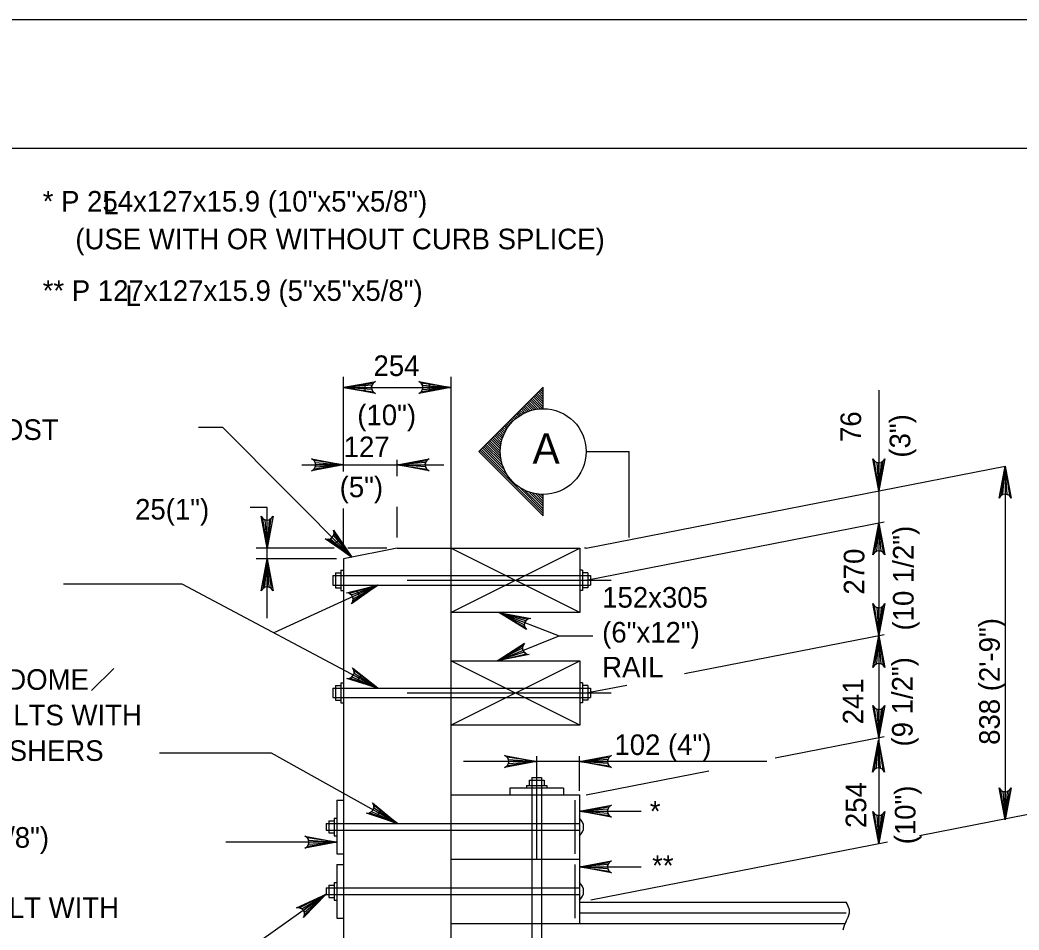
# Model space of a CAD drawing. Extents: x 0 to 36.3, y -66 to 0.
# Drawn here: x 5.26 to 11.08, y -5.3 to 0 of the extents above; entities that cross this region are included whole.
import ezdxf

# ---------------------------------------------------------------- set-up
doc = ezdxf.new("R2010")
doc.units = 0
for name, color, linetype in [('1', 7, 'Continuous'), ('2', 7, 'Continuous'), ('3', 7, 'Continuous'), ('63', 7, 'Continuous')]:
    doc.layers.add(name, color=color, linetype=linetype)

msp = doc.modelspace()

# ---------------------------------------------------------------- linework, layer by layer
at = {"layer": '1'}
msp.add_lwpolyline([(1.75, -21.25), (33.25, -21.25), (33.25, -0.75), (1.75, -0.75)], close=True, dxfattribs=at)
at = {"layer": '2'}
for p, q in [((7.4603, -3.0782), (7.1478, -3.1407)), ((7.4603, -3.0782), (7.7728, -3.0782)), ((8.5244, -3.4532), (7.7728, -3.0782)), ((7.7728, -3.4532), (8.5244, -3.0782)), ((7.7728, -3.0782), (7.7728, -6.0157)), ((7.7728, -3.0782), (8.5244, -3.0782)), ((8.5244, -3.0782), (8.5244, -3.4532)), ((7.1478, -3.1407), (7.1478, -6.0157)), ((7.0853, -3.2383), (7.0853, -3.293)), ((7.0853, -3.2383), (8.5866, -3.2383)), ((7.101, -3.2227), (7.101, -3.3087)), ((7.101, -3.2227), (7.1322, -3.2227)), ((7.1322, -3.2071), (7.1478, -3.2071)), ((7.1322, -3.2071), (7.1322, -3.3242)), ((8.5397, -3.2071), (8.5241, -3.2071)), ((8.5397, -3.2071), (8.5397, -3.3242)), ((8.571, -3.2227), (8.5397, -3.2227)), ((8.571, -3.2227), (8.571, -3.3087)), ((8.5866, -3.2383), (8.5866, -3.293)), ((7.0853, -3.293), (8.5866, -3.293)), ((7.101, -3.3087), (7.1322, -3.3087)), ((8.571, -3.3087), (8.5397, -3.3087)), ((7.1322, -3.3242), (7.1478, -3.3242)), ((8.5397, -3.3242), (8.5241, -3.3242)), ((8.5244, -3.4532), (7.7728, -3.4532)), ((7.7728, -4.1094), (8.5244, -3.7344)), ((8.5244, -4.1094), (7.7728, -3.7344)), ((7.7728, -3.7344), (8.5244, -3.7344)), ((8.5244, -3.7344), (8.5244, -4.1094)), ((7.0853, -3.8946), (7.0853, -3.9492)), ((7.0853, -3.8946), (8.5866, -3.8946)), ((7.101, -3.8789), (7.1322, -3.8789)), ((7.101, -3.8789), (7.101, -3.9649)), ((7.1322, -3.8633), (7.1322, -3.9805)), ((7.1322, -3.8633), (7.1478, -3.8633)), ((8.5397, -3.8633), (8.5241, -3.8633)), ((8.5397, -3.8633), (8.5397, -3.9805)), ((8.571, -3.8789), (8.5397, -3.8789)), ((8.571, -3.8789), (8.571, -3.9649)), ((8.5866, -3.8946), (8.5866, -3.9492)), ((7.0853, -3.9492), (8.5866, -3.9492)), ((7.101, -3.9649), (7.1322, -3.9649)), ((7.1322, -3.9805), (7.1478, -3.9805)), ((8.5397, -3.9805), (8.5241, -3.9805)), ((8.571, -3.9649), (8.5397, -3.9649)), ((8.5244, -4.1094), (7.7728, -4.1094)), ((8.2453, -4.4141), (8.3001, -4.4141)), ((8.2453, -4.4141), (8.2453, -6.1172)), ((8.3001, -4.4141), (8.3001, -6.1172)), ((8.429, -4.4766), (8.1165, -4.4766)), ((8.1165, -4.4766), (8.1165, -4.5157)), ((8.2141, -4.461), (8.3313, -4.461)), ((8.2141, -4.461), (8.2141, -4.4766)), ((8.2297, -4.4297), (8.2297, -4.461)), ((8.2297, -4.4297), (8.3157, -4.4297)), ((8.3157, -4.4297), (8.3157, -4.461)), ((8.3313, -4.461), (8.3313, -4.4766)), ((8.429, -4.4766), (8.429, -4.5157)), ((7.7728, -4.5157), (8.5228, -4.5157)), ((8.5228, -4.5157), (8.5228, -4.8907)), ((7.1087, -4.5469), (7.1087, -4.8594)), ((7.1087, -4.5469), (7.1478, -4.5469)), ((8.4949, -4.5469), (8.4949, -4.8594)), ((7.0932, -4.6524), (7.0932, -4.7539)), ((7.0932, -4.6524), (7.1087, -4.6524)), ((7.0462, -4.6837), (7.0462, -4.7227)), ((7.0462, -4.6837), (8.5228, -4.6837)), ((7.0619, -4.668), (7.0932, -4.668)), ((7.0619, -4.668), (7.0619, -4.7383)), ((7.0462, -4.7227), (8.5228, -4.7227)), ((7.0619, -4.7383), (7.0932, -4.7383)), ((7.0932, -4.7539), (7.1087, -4.7539)), ((7.1087, -4.8594), (7.1478, -4.8594)), ((7.1087, -4.9219), (7.1087, -5.2344)), ((7.1087, -4.9219), (7.1478, -4.9219)), ((7.7728, -4.8907), (8.5228, -4.8907)), ((8.4949, -4.9219), (8.4949, -5.2344)), ((8.5228, -4.8907), (8.5228, -5.2657)), ((7.0462, -5.0587), (7.0462, -5.0977)), ((7.0462, -5.0587), (8.5228, -5.0587)), ((7.0619, -5.043), (7.0932, -5.043)), ((7.0619, -5.043), (7.0619, -5.1133)), ((7.0932, -5.0274), (7.0932, -5.1289)), ((7.0932, -5.0274), (7.1087, -5.0274)), ((7.0462, -5.0977), (8.5228, -5.0977)), ((7.0619, -5.1133), (7.0932, -5.1133)), ((7.0932, -5.1289), (7.1087, -5.1289)), ((8.5228, -5.1407), (10.0762, -5.1407)), ((7.1087, -5.2344), (7.1478, -5.2344)), ((8.5228, -5.2032), (10.0762, -5.2032)), ((7.7728, -5.2657), (10.0695, -5.2657))]:
    msp.add_line(p, q, dxfattribs=at)
for centre, radius, start, end in [((8.4804, -4.7032), 0.0661, 309.84987, 50.15014), ((8.4804, -5.0782), 0.0661, 309.84987, 50.15014), ((9.9246, -5.2324), 0.1772, 16.85937, 31.17642), ((9.9442, -5.1737), 0.154, 329.0266, 348.78562), ((10.0494, -5.1946), 0.0468, 348.78562, 16.85937), ((10.2172, -5.3375), 0.1643, 149.0266, 168.1522)]:
    msp.add_arc(centre, radius, start, end, dxfattribs=at)
at = {"layer": '3'}
for p, q in [((7.1478, -2.6309), (7.1478, -2.0793)), ((7.7728, -2.0793), (7.7728, -3.0782)), ((7.1478, -2.1418), (7.7728, -2.1418)), ((7.9362, -2.5156), (8.3112, -2.1406)), ((8.3039, -2.1479), (8.3112, -2.1552)), ((8.3112, -2.2656), (8.3112, -2.1406)), ((8.2402, -2.2115), (8.2948, -2.2661)), ((8.2473, -2.2044), (8.3085, -2.2656)), ((8.2544, -2.1973), (8.3112, -2.2542)), ((8.2615, -2.1903), (8.3112, -2.24)), ((8.2686, -2.1833), (8.3112, -2.2259)), ((8.2757, -2.1762), (8.3112, -2.2117)), ((8.2827, -2.1691), (8.3112, -2.1976)), ((8.2897, -2.162), (8.3112, -2.1835)), ((8.2968, -2.1549), (8.3112, -2.1693)), ((10.2672, -2.1583), (10.2672, -4.799)), ((8.1837, -2.2681), (8.2049, -2.2893)), ((8.1907, -2.261), (8.2148, -2.2849)), ((8.1978, -2.2539), (8.2248, -2.281)), ((8.2049, -2.2468), (8.2354, -2.2773)), ((8.212, -2.2398), (8.2463, -2.2742)), ((8.2191, -2.2327), (8.2577, -2.2713)), ((8.2262, -2.2257), (8.2698, -2.2692)), ((8.2332, -2.2186), (8.2819, -2.2673)), ((8.1272, -2.3247), (8.1379, -2.3354)), ((8.1342, -2.3176), (8.1452, -2.3286)), ((8.1412, -2.3105), (8.1529, -2.3221)), ((8.1483, -2.3034), (8.1608, -2.3159)), ((8.1554, -2.2963), (8.169, -2.31)), ((8.1625, -2.2893), (8.1775, -2.3043)), ((8.1696, -2.2822), (8.1863, -2.299)), ((8.1767, -2.2752), (8.1955, -2.294)), ((6.4452, -2.3756), (6.303, -2.3756)), ((7.1963, -3.131), (6.4452, -2.3756)), ((8.0706, -2.3813), (8.0895, -2.4001)), ((8.0777, -2.3742), (8.0945, -2.391)), ((8.0847, -2.3671), (8.0998, -2.3822)), ((8.0917, -2.36), (8.1054, -2.3737)), ((8.0988, -2.3529), (8.1113, -2.3654)), ((8.1059, -2.3458), (8.1176, -2.3575)), ((8.113, -2.3388), (8.1241, -2.3498)), ((8.1201, -2.3317), (8.1308, -2.3425)), ((8.014, -2.4377), (8.0629, -2.4867)), ((8.0211, -2.4307), (8.0647, -2.4743)), ((8.0282, -2.4237), (8.0669, -2.4624)), ((8.0352, -2.4166), (8.0697, -2.4511)), ((8.0422, -2.4095), (8.0729, -2.4401)), ((8.0493, -2.4024), (8.0765, -2.4296)), ((8.0564, -2.3953), (8.0805, -2.4194)), ((8.0635, -2.3883), (8.0848, -2.4096)), ((7.9503, -2.5014), (8.1032, -2.6543)), ((7.9574, -2.4943), (8.0849, -2.6218)), ((7.9645, -2.4872), (8.0752, -2.598)), ((7.9716, -2.4802), (8.0691, -2.5777)), ((7.9787, -2.4732), (8.0652, -2.5597)), ((7.9857, -2.4661), (8.0627, -2.5431)), ((7.9928, -2.459), (8.0615, -2.5277)), ((7.9998, -2.4519), (8.0612, -2.5133)), ((8.0069, -2.4448), (8.0617, -2.4997)), ((7.9362, -2.5156), (8.3112, -2.8906)), ((7.9433, -2.5085), (8.3112, -2.8764)), ((8.5612, -2.5156), (8.8112, -2.5156)), ((8.8112, -3.0156), (8.8112, -2.5156)), ((6.9047, -2.592), (7.7328, -2.592)), ((7.4603, -2.6589), (7.4603, -2.5627)), ((8.5619, -3.0782), (11.0025, -2.6002)), ((11.0025, -2.6002), (11.0025, -4.6612)), ((8.1725, -2.7235), (8.3112, -2.8622)), ((8.2049, -2.7418), (8.3112, -2.8482)), ((8.2288, -2.7516), (8.3112, -2.834)), ((8.2491, -2.7577), (8.3112, -2.8198)), ((8.2672, -2.7617), (8.3112, -2.8057)), ((8.2837, -2.7641), (8.3112, -2.7916)), ((8.2991, -2.7652), (8.3112, -2.7774)), ((8.3112, -2.8906), (8.3112, -2.7656)), ((6.7019, -2.8413), (6.603, -2.8413)), ((6.7019, -3.4869), (6.7019, -2.8413)), ((7.1478, -3.0563), (7.1478, -2.8473)), ((7.4603, -3.0157), (7.4603, -2.8381)), ((8.5619, -3.2657), (10.2984, -2.9256)), ((7.0938, -3.0782), (6.6394, -3.0782)), ((7.3998, -3.0782), (7.1719, -3.0782)), ((8.5619, -3.0782), (8.5525, -3.0782)), ((7.1065, -3.1407), (6.6394, -3.1407)), ((6.2074, -3.2883), (5.5168, -3.2883)), ((7.3482, -3.8946), (6.2074, -3.2883)), ((7.3482, -3.293), (6.742, -3.5724)), ((7.5183, -3.2657), (8.7078, -3.2657)), ((8.052, -3.4532), (8.4034, -3.5896)), ((8.0424, -3.7344), (8.4034, -3.5896)), ((8.4034, -3.5896), (8.6007, -3.5896)), ((9.1351, -3.8097), (10.2984, -3.5818)), ((5.6796, -3.9082), (5.809, -3.7788)), ((8.5619, -3.9219), (8.7973, -3.8758)), ((7.5183, -3.9219), (8.7078, -3.9219)), ((9.6619, -4.3002), (10.2984, -4.1756)), ((6.7277, -4.2723), (6.0758, -4.2723)), ((7.4611, -4.6837), (6.7277, -4.2723)), ((8.2728, -4.2905), (8.2728, -4.8907)), ((8.5228, -4.4917), (8.5228, -4.2905)), ((9.6141, -4.3217), (7.8459, -4.3217)), ((8.5619, -4.5157), (9.2757, -4.3759)), ((8.5228, -4.6114), (8.8809, -4.6114)), ((10.5034, -4.7528), (11.1361, -4.6288)), ((7.1087, -4.7919), (6.4625, -4.7919)), ((8.5891, -5.1277), (10.317, -4.7893)), ((8.5228, -4.9351), (8.8809, -4.9351)), ((7.0462, -5.0949), (6.6647, -5.3667))]:
    msp.add_line(p, q, dxfattribs=at)
for points in [[(7.1478, -2.1418), (7.3342, -2.1069), (7.3199, -2.1168), (7.3125, -2.1293), (7.3103, -2.1418), (7.3125, -2.1543), (7.3199, -2.1668), (7.3342, -2.1767), (7.1478, -2.1418), (7.3199, -2.1668), (7.3125, -2.1543), (7.1478, -2.1418), (7.3103, -2.1418), (7.3125, -2.1293), (7.1478, -2.1418), (7.3199, -2.1168)], [(7.7728, -2.1418), (7.5864, -2.1767), (7.6007, -2.1668), (7.6082, -2.1543), (7.6103, -2.1418), (7.6082, -2.1293), (7.6007, -2.1168), (7.5864, -2.1069), (7.7728, -2.1418), (7.6007, -2.1168), (7.6082, -2.1293), (7.7728, -2.1418), (7.6103, -2.1418), (7.6082, -2.1543), (7.7728, -2.1418), (7.6007, -2.1668)], [(7.1478, -2.592), (6.9614, -2.6269), (6.9757, -2.617), (6.9832, -2.6045), (6.9853, -2.592), (6.9832, -2.5795), (6.9757, -2.567), (6.9614, -2.5571), (7.1478, -2.592), (6.9757, -2.567), (6.9832, -2.5795), (7.1478, -2.592), (6.9853, -2.592), (6.9832, -2.6045), (7.1478, -2.592), (6.9757, -2.617)], [(7.4603, -2.592), (7.6467, -2.5571), (7.6324, -2.567), (7.625, -2.5795), (7.6228, -2.592), (7.625, -2.6045), (7.6324, -2.617), (7.6467, -2.6269), (7.4603, -2.592), (7.6324, -2.617), (7.625, -2.6045), (7.4603, -2.592), (7.6228, -2.592), (7.625, -2.5795), (7.4603, -2.592), (7.6324, -2.567)], [(10.2672, -2.7442), (10.2323, -2.5577), (10.2422, -2.5722), (10.2547, -2.5795), (10.2672, -2.5817), (10.2797, -2.5795), (10.2922, -2.5722), (10.3021, -2.5577), (10.2672, -2.7442), (10.2922, -2.5722), (10.2797, -2.5795), (10.2672, -2.7442), (10.2672, -2.5817), (10.2547, -2.5795), (10.2672, -2.7442), (10.2422, -2.5722)], [(11.0025, -2.6002), (11.0374, -2.7866), (11.0275, -2.7723), (11.015, -2.7648), (11.0025, -2.7627), (10.99, -2.7648), (10.9775, -2.7723), (10.9676, -2.7866), (11.0025, -2.6002), (10.9775, -2.7723), (10.99, -2.7648), (11.0025, -2.6002), (11.0025, -2.7627), (11.015, -2.7648), (11.0025, -2.6002), (11.0275, -2.7723)], [(6.7019, -3.0782), (6.667, -2.8918), (6.6769, -2.9061), (6.6894, -2.9135), (6.7019, -2.9157), (6.7144, -2.9135), (6.7269, -2.9061), (6.7368, -2.8918), (6.7019, -3.0782), (6.7269, -2.9061), (6.7144, -2.9135), (6.7019, -3.0782), (6.7019, -2.9157), (6.6894, -2.9135), (6.7019, -3.0782), (6.6769, -2.9061)], [(10.2672, -2.9317), (10.3021, -3.1181), (10.2922, -3.1037), (10.2797, -3.0963), (10.2672, -3.0942), (10.2547, -3.0963), (10.2422, -3.1037), (10.2322, -3.1181), (10.2672, -2.9317), (10.2422, -3.1037), (10.2547, -3.0963), (10.2672, -2.9317), (10.2672, -3.0942), (10.2797, -3.0963), (10.2672, -2.9317), (10.2922, -3.1037)], [(7.1963, -3.131), (7.0401, -3.0234), (7.0573, -3.0266), (7.0714, -3.0231), (7.0817, -3.0157), (7.0891, -3.0054), (7.0927, -2.9913), (7.0897, -2.9742), (7.1963, -3.131), (7.0927, -2.9913), (7.0891, -3.0054), (7.1963, -3.131), (7.0817, -3.0157), (7.0714, -3.0231), (7.1963, -3.131), (7.0573, -3.0266)], [(6.7019, -3.1407), (6.7368, -3.3271), (6.7269, -3.3127), (6.7144, -3.3053), (6.7019, -3.3032), (6.6894, -3.3053), (6.6769, -3.3127), (6.667, -3.3271), (6.7019, -3.1407), (6.6769, -3.3127), (6.6894, -3.3053), (6.7019, -3.1407), (6.7019, -3.3032), (6.7144, -3.3053), (6.7019, -3.1407), (6.7269, -3.3127)], [(7.3482, -3.293), (7.1935, -3.4027), (7.2024, -3.3878), (7.2039, -3.3733), (7.2006, -3.361), (7.1934, -3.3506), (7.1814, -3.3423), (7.1643, -3.3393), (7.3482, -3.293), (7.1814, -3.3423), (7.1934, -3.3506), (7.3482, -3.293), (7.2006, -3.361), (7.2039, -3.3733), (7.3482, -3.293), (7.2024, -3.3878)], [(10.2672, -3.5879), (10.2323, -3.4015), (10.2422, -3.4158), (10.2547, -3.4232), (10.2672, -3.4254), (10.2797, -3.4232), (10.2922, -3.4158), (10.3021, -3.4015), (10.2672, -3.5879), (10.2922, -3.4158), (10.2797, -3.4232), (10.2672, -3.5879), (10.2672, -3.4254), (10.2547, -3.4232), (10.2672, -3.5879), (10.2422, -3.4158)], [(8.052, -3.4532), (8.2384, -3.4881), (8.2214, -3.4921), (8.21, -3.5011), (8.2035, -3.512), (8.201, -3.5244), (8.2033, -3.5387), (8.2132, -3.5532), (8.052, -3.4532), (8.2033, -3.5387), (8.201, -3.5244), (8.052, -3.4532), (8.2035, -3.512), (8.21, -3.5011), (8.052, -3.4532), (8.2214, -3.4921)], [(10.2672, -3.5879), (10.3021, -3.7743), (10.2922, -3.76), (10.2797, -3.7526), (10.2672, -3.7504), (10.2547, -3.7526), (10.2422, -3.76), (10.2322, -3.7743), (10.2672, -3.5879), (10.2422, -3.76), (10.2547, -3.7526), (10.2672, -3.5879), (10.2672, -3.7504), (10.2797, -3.7526), (10.2672, -3.5879), (10.2922, -3.76)], [(8.0424, -3.7344), (8.2024, -3.6326), (8.1928, -3.6472), (8.1906, -3.6615), (8.1932, -3.6739), (8.1999, -3.6847), (8.2114, -3.6936), (8.2284, -3.6974), (8.0424, -3.7344), (8.2114, -3.6936), (8.1999, -3.6847), (8.0424, -3.7344), (8.1932, -3.6739), (8.1906, -3.6615), (8.0424, -3.7344), (8.1928, -3.6472)], [(7.3482, -3.8946), (7.1672, -3.838), (7.1845, -3.8359), (7.1969, -3.8283), (7.2047, -3.8183), (7.2087, -3.8062), (7.208, -3.7917), (7.1999, -3.7762), (7.3482, -3.8946), (7.208, -3.7917), (7.2087, -3.8062), (7.3482, -3.8946), (7.2047, -3.8183), (7.1969, -3.8283), (7.3482, -3.8946), (7.1845, -3.8359)], [(10.2672, -4.1817), (10.2323, -3.9952), (10.2422, -4.0096), (10.2547, -4.017), (10.2672, -4.0192), (10.2797, -4.017), (10.2922, -4.0096), (10.3021, -3.9952), (10.2672, -4.1817), (10.2922, -4.0096), (10.2797, -4.017), (10.2672, -4.1817), (10.2672, -4.0192), (10.2547, -4.017), (10.2672, -4.1817), (10.2422, -4.0096)], [(10.2647, -4.1965), (10.2997, -4.3829), (10.2897, -4.3686), (10.2772, -4.3612), (10.2647, -4.359), (10.2522, -4.3612), (10.2397, -4.3686), (10.2297, -4.3829), (10.2647, -4.1965), (10.2397, -4.3686), (10.2522, -4.3612), (10.2647, -4.1965), (10.2647, -4.359), (10.2772, -4.3612), (10.2647, -4.1965), (10.2897, -4.3686)], [(8.2728, -4.3217), (8.0864, -4.3567), (8.1007, -4.3468), (8.1082, -4.3342), (8.1103, -4.3217), (8.1082, -4.3092), (8.1007, -4.2968), (8.0864, -4.2868), (8.2728, -4.3217), (8.1007, -4.2968), (8.1082, -4.3092), (8.2728, -4.3217), (8.1103, -4.3217), (8.1082, -4.3342), (8.2728, -4.3217), (8.1007, -4.3468)], [(8.5228, -4.3217), (8.7092, -4.2868), (8.6949, -4.2968), (8.6875, -4.3092), (8.6853, -4.3217), (8.6875, -4.3342), (8.6949, -4.3468), (8.7092, -4.3567), (8.5228, -4.3217), (8.6949, -4.3468), (8.6875, -4.3342), (8.5228, -4.3217), (8.6853, -4.3217), (8.6875, -4.3092), (8.5228, -4.3217), (8.6949, -4.2968)], [(11.0025, -4.6611), (10.9676, -4.4747), (10.9775, -4.4891), (10.99, -4.4965), (11.0025, -4.4986), (11.015, -4.4965), (11.0275, -4.4891), (11.0374, -4.4747), (11.0025, -4.6611), (11.0275, -4.4891), (11.015, -4.4965), (11.0025, -4.6611), (11.0025, -4.4986), (10.99, -4.4965), (11.0025, -4.6611), (10.9775, -4.4891)], [(7.4611, -4.6837), (7.2814, -4.623), (7.2988, -4.6213), (7.3113, -4.614), (7.3193, -4.6042), (7.3236, -4.5922), (7.3232, -4.5777), (7.3156, -4.562), (7.4611, -4.6837), (7.3232, -4.5777), (7.3236, -4.5922), (7.4611, -4.6837), (7.3193, -4.6042), (7.3113, -4.614), (7.4611, -4.6837), (7.2988, -4.6213)], [(8.5228, -4.6114), (8.7092, -4.5765), (8.6949, -4.5864), (8.6875, -4.5989), (8.6853, -4.6114), (8.6875, -4.6239), (8.6949, -4.6364), (8.7092, -4.6463), (8.5228, -4.6114), (8.6949, -4.6364), (8.6875, -4.6239), (8.5228, -4.6114), (8.6853, -4.6114), (8.6875, -4.5989), (8.5228, -4.6114), (8.6949, -4.5864)], [(10.2672, -4.799), (10.2323, -4.6126), (10.2422, -4.6269), (10.2547, -4.6343), (10.2672, -4.6365), (10.2797, -4.6343), (10.2922, -4.6269), (10.3021, -4.6126), (10.2672, -4.799), (10.2922, -4.6269), (10.2797, -4.6343), (10.2672, -4.799), (10.2672, -4.6365), (10.2547, -4.6343), (10.2672, -4.799), (10.2422, -4.6269)], [(7.1087, -4.7919), (6.9223, -4.8268), (6.9367, -4.8169), (6.9441, -4.8044), (6.9463, -4.7919), (6.9441, -4.7794), (6.9367, -4.7669), (6.9223, -4.757), (7.1087, -4.7919), (6.9367, -4.7669), (6.9441, -4.7794), (7.1087, -4.7919), (6.9463, -4.7919), (6.9441, -4.8044), (7.1087, -4.7919), (6.9367, -4.8169)], [(8.5228, -4.9351), (8.7092, -4.9002), (8.6949, -4.9101), (8.6875, -4.9226), (8.6853, -4.9351), (8.6875, -4.9476), (8.6949, -4.9601), (8.7092, -4.97), (8.5228, -4.9351), (8.6949, -4.9601), (8.6875, -4.9476), (8.5228, -4.9351), (8.6853, -4.9351), (8.6875, -4.9226), (8.5228, -4.9351), (8.6949, -4.9101)], [(7.0462, -5.0949), (6.9147, -5.2316), (6.9207, -5.2151), (6.9194, -5.2007), (6.9139, -5.1892), (6.9049, -5.1803), (6.8916, -5.1744), (6.8742, -5.1746), (7.0462, -5.0949), (6.8916, -5.1744), (6.9049, -5.1803), (7.0462, -5.0949), (6.9139, -5.1892), (6.9194, -5.2007), (7.0462, -5.0949), (6.9207, -5.2151)]]:
    msp.add_lwpolyline(points, dxfattribs=at)
for points in [[(7.2728, -2.1627), (7.2728, -2.121), (7.1478, -2.1418)], [(7.6478, -2.1627), (7.6478, -2.121), (7.7728, -2.1418)], [(7.1229, -3.0277), (7.0934, -3.057), (7.1963, -3.131)], [(7.2259, -3.3264), (7.2433, -3.3642), (7.3482, -3.293)], [(7.2476, -3.8175), (7.228, -3.8543), (7.3482, -3.8946)], [(7.3622, -4.6043), (7.3417, -4.6407), (7.461, -4.6837)]]:
    msp.add_lwpolyline(points, close=True, dxfattribs=at)
msp.add_circle((8.3112, -2.5156), 0.25, dxfattribs=at)
at = {"layer": '63'}
msp.add_lwpolyline([(0, -22), (34, -22), (34, 0), (0, 0)], close=True, dxfattribs=at)

# ---------------------------------------------------------------- texts
at = {"layer": '3'}
for s, height, p in [(' * P 254x127x15.9 (10"x5"x5/8")', 0.12, (5.3502, -1.1166)), ('L', 0.12, (5.7473, -1.1318)), (' (USE WITH OR WITHOUT CURB SPLICE)', 0.12, (5.5405, -1.3364)), (' ** P 127x127x15.9 (5"x5"x5/8")', 0.12, (5.3502, -1.6372)), ('L', 0.12, (5.877, -1.6662)), ('254', 0.12, (7.3223, -2.075)), ('(10")', 0.12, (7.2279, -2.3617)), ('254x305 (10"x12")POST', 0.12, (3.7323, -2.4477)), ('127', 0.12, (7.1483, -2.5477)), ('A', 0.1772, (8.249, -2.5857)), ('(5")', 0.12, (7.125, -2.7814)), ('25(1")', 0.12, (5.9332, -2.9116)), ('152x305', 0.12, (8.6547, -3.425)), ('(6"x12")', 0.12, (8.6547, -3.6283)), ('RAIL', 0.12, (8.6547, -3.8317)), ('2 EA. 25.4(1")0 DOME', 0.12, (4.0463, -3.9038)), ('HEAD BOLTS WITH', 0.12, (4.5013, -4.111)), ('102 (4")', 0.12, (8.7259, -4.284)), ('FLAT WASHERS', 0.12, (4.5013, -4.3182)), ('*', 0.12, (8.9321, -4.6713)), ('P 254x127x15.9 (10"x5"x5/8")', 0.12, (3.2983, -4.8241)), ('**', 0.12, (8.9453, -4.9879)), ('15.9(5/8")0 DOME HEAD BOLT WITH', 0.12, (3.1162, -5.2331))]:
    msp.add_text(s, height=height, dxfattribs=at).set_placement(p)
for s, p in [('76', (10.1631, -2.4595)), ('(3")', (10.4497, -2.5507)), ('(10 1/2")', (10.469, -3.558)), ('270', (10.1823, -3.3488)), ('838 (2\'-9")', (10.9712, -4.2245)), ('(9 1/2")', (10.4633, -4.2342)), ('241', (10.1766, -4.1052)), ('254', (10.1932, -4.7097)), ('(10")', (10.4799, -4.8042))]:
    msp.add_text(s, height=0.12, rotation=90, dxfattribs=at).set_placement(p)

doc.saveas('drawing.dxf')
